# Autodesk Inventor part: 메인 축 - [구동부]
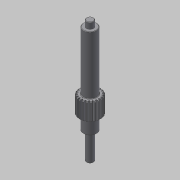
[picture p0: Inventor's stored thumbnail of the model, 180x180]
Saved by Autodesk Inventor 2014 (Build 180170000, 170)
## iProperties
Created: 2016-02
Part Number: 메인 축 - [구동부]
Material: 일반
Document SubType Name: Modeling
Categories: <?xml version="1.0" encoding="UTF-16"?> <MemberInstance><Categories><FamilyTemplate><FamilyTemplateParameter ValueType="xs:double" Id="1" ObjectReferenceKey="da
Density: 1 g/cm^3
Mass: 187.503 g
Surface Area: 82.0529 cm^2
Volume: 23.8554 cm^3
Appearance: 기본값
Author: mdu
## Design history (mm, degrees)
sketch "Sketch1"
  geometry: C1 r 12 at (0, 0)
  constraints: 1 centre point
  dimensions: "d0" = 24 diameter of C1 (= da_da)
extrude "Extrusion1" new body sketch "Sketch1" distance "d1" = 20 (= da_b); taper "d2" = 0 deg
workplane "Work Plane2"
feature "피치 지름" dims "d4" = 10, "d5" = 0
workplane "Work Plane8"
workplane "Work Plane9"
chamfer "모따기1" distance "d49" = 1; stored, may be unused: second distance "d50" = 2, angle "d51" = 45 deg
sketch "스케치3"
  geometry: C1 r 7.5 at (0, 0); 1 further point
  constraints: 1 centre point, 1 coincident
  dimensions: "d52" = 15 diameter of C1
extrude "돌출2" join sketch "스케치3" distance "d53" = 66; taper "d54" = 0 deg
sketch "스케치4"
  geometry: C1 r 4 at (0, 0); 1 further point
  constraints: 1 centre point, 1 coincident
  dimensions: "d55" = 8 diameter of C1
extrude "돌출3" join sketch "스케치4" distance "d56" = 7; taper "d57" = 0 deg
sketch "스케치5"
  geometry: C1 r 7.5 at (0, 0) reference; C2 r 7.5 at (0, 0) reference; 1 further point
extrude "돌출4" join sketch "스케치5" distance "d62" = 16; taper "d63" = 0 deg
sketch "스케치6"
  geometry: C1 r 4 at (0, 0); 1 further point
  constraints: 1 centre point, 1 coincident
  dimensions: "d64" = 8 diameter of C1
extrude "돌출5" join sketch "스케치6" distance "d65" = 30; taper "d66" = 0 deg
chamfer "모따기2" distance "d58" = 0.5; stored, may be unused: second distance "d59" = 2, angle "d60" = 45 deg
fillet "모깎기1" dims "d61" = 0.5
feature "스퍼 기어" dims "da_b" = 20, "da_d" = 22, "da_aw" = 31, "da_da" = 24, "da_df" = 19.5, "da_dw" = 22, angle "da_beta" = 0 deg, "da_lefttooth" = 0, "da_righttooth" = 0
sketch "스케치7" dims "d68" = 18
  geometry: C1 r 0.25 at (0, -9); 2 further points
  constraints: 2 vertical alignment, 1 centre point, 1 coincident, 2 other
  dimensions: "d67" = 0.5 diameter of C1
extrude "돌출6" join sketch "스케치7" distance "d69" = 0.3; taper "d70" = 0 deg
body "Solid1"
sketch "Sketch2"
  geometry: C1 r 12 at (0, 0) reference; C2 r 11 at (0, 0)
  constraints: 1 centre point, 1 coincident
  dimensions: "d3" = 22 diameter of C2 (= da_dw)
body "Srf1"
node "투영된 루프1"
other parameters: "d16" = 31 (= da_aw), "d17" = 0, "d34" = 1.428 (computed from da_z), "d39" = 0, "d41" = 0, "d43" = 31 (= da_aw), "d46" = 31 (= da_aw), "d47" = 0, "d48" = 0
